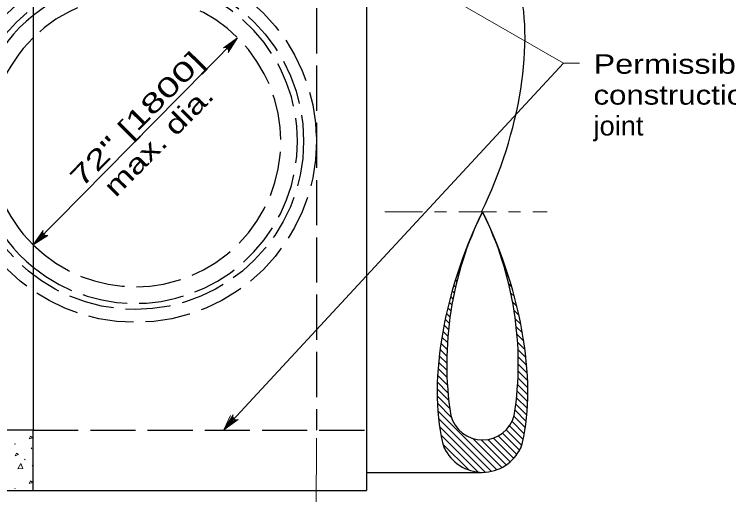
# Model space of a CAD drawing. Extents: x 1073.4 to 1107.4, y 719.4 to 741.4.
# Drawn here: x 1078.83 to 1084.72, y 723.51 to 727.47 of the extents above; entities that cross this region are included whole.
import ezdxf
from ezdxf.enums import TextEntityAlignment as Align

# ---------------------------------------------------------------- set-up
doc = ezdxf.new("R2010")
doc.units = 0
doc.header["$LTSCALE"] = 0.062
doc.linetypes.add('DOT_DASHED', pattern=[7.7, 5, -1.2, 0.3, -1.2])
doc.linetypes.add('LONG_DASHED', pattern=[7.5, 6, -1.5])
doc.layers.add('1', color=7, linetype='Continuous', lineweight=13)

msp = doc.modelspace()

# ---------------------------------------------------------------- linework, layer by layer
at = {"layer": '1', "lineweight": 25}
for p, q in [((1081.73483, 728.71742), (1081.73483, 723.54533)), ((1078.98608, 727.99275), (1078.98608, 724.04508)), ((1081.73483, 723.69525), (1082.68442, 723.69525)), ((1077.93658, 723.54533), (1081.73483, 723.54533)), ((1078.98608, 723.54533), (1081.73483, 723.54533))]:
    msp.add_line(p, q, dxfattribs=at)
at = {"layer": '1', "linetype": 'LONG_DASHED', "lineweight": 25}
for p, q in [((1081.3225, 727.99275), (1081.3225, 724.04508)), ((1078.98608, 724.04508), (1081.73483, 724.04508))]:
    msp.add_line(p, q, dxfattribs=at)
at = {"layer": '1'}
for p, q in [((1080.56908, 727.19733), (1080.67292, 727.27758)), ((1080.5785, 727.19517), (1080.67292, 727.27758)), ((1080.58842, 727.18883), (1080.67292, 727.27758)), ((1080.59408, 727.18167), (1080.67292, 727.27758)), ((1080.59742, 727.17242), (1080.67292, 727.27758)), ((1083.35958, 727.06742), (1080.55975, 724.04658)), ((1082.68, 725.84342), (1082.67692, 725.844)), ((1082.69183, 725.844), (1082.68875, 725.84342)), ((1082.70842, 725.80133), (1082.71117, 725.80408)), ((1082.73408, 725.74608), (1082.73667, 725.74867)), ((1079.06642, 725.67367), (1078.98608, 725.57217)), ((1079.06942, 725.66425), (1078.98608, 725.57217)), ((1079.07475, 725.65675), (1078.98608, 725.57217)), ((1079.08442, 725.65), (1078.98608, 725.57217)), ((1079.09367, 725.64742), (1078.98608, 725.57217)), ((1082.54625, 725.495), (1082.54233, 725.49892)), ((1082.53175, 725.45125), (1082.52667, 725.45642)), ((1082.859, 725.45125), (1082.84875, 725.46142)), ((1082.51783, 725.40692), (1082.51142, 725.41333)), ((1082.492, 725.31633), (1082.48225, 725.32608)), ((1082.50467, 725.36192), (1082.49667, 725.36992)), ((1082.90692, 725.30892), (1082.88892, 725.32692)), ((1082.48008, 725.27), (1082.46842, 725.28167)), ((1082.46875, 725.22308), (1082.45492, 725.23692)), ((1082.93217, 725.22558), (1082.90892, 725.24883)), ((1082.44842, 725.127), (1082.42942, 725.14592)), ((1082.45817, 725.17542), (1082.442, 725.19167)), ((1082.95467, 725.14492), (1082.926, 725.1735)), ((1082.43933, 725.07783), (1082.41742, 725.09975)), ((1082.9745, 725.06675), (1082.94033, 725.101)), ((1082.431, 725.02792), (1082.406, 725.05292)), ((1082.99208, 724.991), (1082.95242, 725.03067)), ((1082.4235, 724.97717), (1082.395, 725.00575)), ((1082.41108, 724.87317), (1082.37475, 724.90942)), ((1082.41683, 724.92558), (1082.38458, 724.95783)), ((1083.00742, 724.91742), (1082.96233, 724.9625)), ((1082.40617, 724.81975), (1082.36558, 724.86042)), ((1083.02075, 724.84575), (1082.97042, 724.89625)), ((1082.40233, 724.76542), (1082.357, 724.81075)), ((1083.03225, 724.77608), (1082.97667, 724.83175)), ((1082.39942, 724.71008), (1082.34908, 724.76042)), ((1083.042, 724.70808), (1082.98133, 724.76883)), ((1082.39767, 724.65367), (1082.342, 724.70925)), ((1083.04992, 724.642), (1082.9845, 724.70742)), ((1082.397, 724.59608), (1082.33558, 724.65742)), ((1083.05625, 724.57742), (1082.98633, 724.64742)), ((1082.39933, 724.47725), (1082.32542, 724.55117)), ((1082.3975, 724.53733), (1082.33, 724.60475)), ((1083.061, 724.51442), (1082.98683, 724.58858)), ((1082.4025, 724.41583), (1082.32175, 724.49658)), ((1083.06417, 724.453), (1082.98617, 724.53108)), ((1082.40725, 724.35283), (1082.31908, 724.441)), ((1083.06583, 724.39308), (1082.98442, 724.47458)), ((1082.4135, 724.28842), (1082.31775, 724.38408)), ((1083.06608, 724.33467), (1082.9815, 724.41925)), ((1082.42158, 724.22208), (1082.31783, 724.32575)), ((1083.06475, 724.27775), (1082.97758, 724.36492)), ((1082.43375, 724.15167), (1082.3195, 724.26583)), ((1083.05775, 724.16825), (1082.967, 724.25908)), ((1083.062, 724.22225), (1082.97275, 724.31158)), ((1082.80958, 723.71767), (1082.323, 724.20417)), ((1083.05208, 724.11567), (1082.96033, 724.2075)), ((1080.61442, 724.16592), (1080.55975, 724.04658)), ((1080.63375, 724.15283), (1080.55975, 724.04658)), ((1080.63742, 724.14358), (1080.55975, 724.04658)), ((1082.76475, 723.70425), (1082.32875, 724.14008)), ((1083.04508, 724.0645), (1082.95192, 724.15767)), ((1080.64308, 724.13642), (1080.55975, 724.04658)), ((1080.65308, 724.13033), (1080.55975, 724.04658)), ((1080.6625, 724.12825), (1080.55975, 724.04658)), ((1083.02642, 723.96675), (1082.91392, 724.07917)), ((1083.03642, 724.01483), (1082.93558, 724.11575)), ((1082.71425, 723.6965), (1082.33742, 724.07333)), ((1083.01475, 723.92008), (1082.88758, 724.04725)), ((1081.3225, 723.97842), (1081.31533, 722.72683)), ((1082.65608, 723.69642), (1082.34975, 724.00275)), ((1082.85008, 723.73542), (1082.60842, 723.97708)), ((1082.88642, 723.75725), (1082.67958, 723.96408)), ((1082.91942, 723.78242), (1082.73467, 723.96725)), ((1082.94908, 723.81108), (1082.78117, 723.979)), ((1082.97533, 723.84308), (1082.82158, 723.99675)), ((1082.99808, 723.87858), (1082.85692, 724.01975)), ((1078.83583, 723.92642), (1078.83942, 723.93442)), ((1082.57808, 723.71625), (1082.36717, 723.92708)), ((1078.97075, 723.89), (1078.97433, 723.898)), ((1078.91642, 723.80442), (1078.92008, 723.79908)), ((1078.97967, 723.74817), (1078.98325, 723.75608)), ((1078.83583, 723.55908), (1078.83942, 723.56708)), ((1078.98608, 723.54533), (1077.93658, 723.54533))]:
    msp.add_line(p, q, dxfattribs=at)
at = {"layer": '1', "linetype": 'DOT_DASHED'}
msp.add_line((1081.88592, 725.844), (1083.22458, 725.844), dxfattribs=at)
at = {"layer": '1'}
for points in [[(1080.95642, 728.45108), (1083.35958, 727.06742), (1083.49042, 727.06742)], [(1078.98608, 725.57217), (1080.18875, 726.78808), (1080.67292, 727.27758)], [(1080.55475, 727.19458), (1080.67292, 727.27758), (1080.59575, 727.1555)], [(1079.10808, 725.64942), (1078.98608, 725.57217), (1079.069, 725.69042)], [(1080.67683, 724.13117), (1080.55975, 724.04658), (1080.63533, 724.16975)], [(1078.85983, 723.72417), (1078.88383, 723.76942), (1078.90242, 723.72775), (1078.86075, 723.72417)]]:
    msp.add_lwpolyline(points, dxfattribs=at)
at = {"layer": '1', "lineweight": 25}
msp.add_lwpolyline([(1078.98608, 723.54533), (1078.98608, 724.04508), (1078.1365, 724.04508), (1078.1365, 723.87017)], dxfattribs=at)
at = {"layer": '1'}
for points in [[(1078.95317, 723.97217), (1078.96383, 723.99433), (1078.98158, 723.98108)], [(1078.83767, 723.83325), (1078.84833, 723.85542), (1078.86608, 723.84208)], [(1078.95317, 723.60483), (1078.96383, 723.62708), (1078.98158, 723.61375)]]:
    msp.add_lwpolyline(points, close=True, dxfattribs=at)
for centre, start, end in [((1080.56738, 727.16676), 338.47635, 114.30248), ((1079.09681, 725.67783), 155.73519, 291.56132), ((1080.66382, 724.15886), 159.26282, 295.08895)]:
    msp.add_arc(centre, 0.03056, start, end, dxfattribs=at)
at = {"layer": '1', "linetype": 'LONG_DASHED', "lineweight": 25}
for centre, major_axis in [((1079.82948, 726.42488), (1.49306, 0)), ((1079.82951, 726.42488), (1.38685, 0))]:
    msp.add_ellipse(centre, major_axis=major_axis, ratio=0.999895, dxfattribs=at)
for major_axis, start_param, end_param in [((1.33687, 0), 4.0297001, 8.5366706), ((1.19944, 0), 3.93253, 8.6338407)]:
    msp.add_ellipse((1079.82951, 726.42488), major_axis=major_axis, ratio=0.999895, start_param=start_param, end_param=end_param, dxfattribs=at)
at = {"layer": '1', "lineweight": 25}
for centre, major_axis, ratio, start_param, end_param in [((1082.13992, 726.52595), (-0.53831, -1.59536), 0.454237, 1.2862985, 2.5699002), ((1079.82951, 726.42488), (1.33687, 0), 0.999895, 2.2534852, 4.0297), ((1079.82951, 726.42488), (1.19944, 0), 0.999895, 2.3506553, 3.93253), ((1083.25027, 725.13915), (0.56019, 1.64146), 0.454236, 1.2862959, 2.5699005), ((1085.2004, 724.59251), (-2.80345, 0), 0.999895, 5.8203513, 6.4360385), ((1080.1834, 724.59251), (2.80345, 0), 0.999895, 6.1303321, 6.7460193), ((1082.13353, 725.13915), (-0.56019, 1.64146), 0.454236, 3.7132848, 4.9968894), ((1082.6919, 724.23514), (0.27133, 0), 0.999895, 3.4004178, 6.0243602), ((1082.69874, 724.05409), (-0.35882, 0), 0.999895, 0.4439383, 1.5517221), ((1082.68506, 724.05409), (0.35882, 0), 0.999895, 4.7314632, 5.839247)]:
    msp.add_ellipse(centre, major_axis=major_axis, ratio=ratio, start_param=start_param, end_param=end_param, dxfattribs=at)
at = {"layer": '1'}
for centre, major_axis, start_param, end_param in [((1082.71916, 724.04819), (-0.35468, 0), 1.4725643, 1.4725644), ((1082.64959, 724.04819), (0.35468, 0), 4.8106209, 4.810621)]:
    msp.add_ellipse(centre, major_axis=major_axis, ratio=0.999895, start_param=start_param, end_param=end_param, dxfattribs=at)

# ---------------------------------------------------------------- texts
for s, width, p in [('72" [1800]', 1.5, (1079.89757, 726.55183)), ('max. dia.', 1.35, (1080.07843, 726.37291))]:
    msp.add_text(s, height=0.16, rotation=45.314, dxfattribs=dict(at, width=width)).set_placement(p, align=Align.CENTER)
for s, width, p in [('Permissible', 1.25, (1083.60733, 726.98125)), ('construction', 1.2, (1083.60733, 726.72683)), ('joint', 1.05, (1083.60733, 726.47242))]:
    msp.add_text(s, height=0.16, dxfattribs=dict(at, width=width)).set_placement(p)

doc.saveas('drawing.dxf')
